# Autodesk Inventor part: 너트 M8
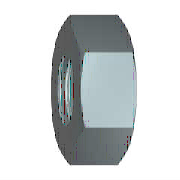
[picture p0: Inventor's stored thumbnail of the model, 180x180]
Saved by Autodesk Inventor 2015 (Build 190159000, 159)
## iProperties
IsCustomPart: 1
Created: 2012-02
Part Number: 너트 M8
Material: 강철, 연강
Description: 6각 너트
Document SubType Name: Modeling
Standard: KS B 1012
Designer: mduedu
Standards Organization: KS
Language: ko-KR
Size Designation: M8
Categories: <MemberInstance><Categories><Category DisplayName="조임쇠" InternalName="e4da775c-781d-43d5-af7c-5136215cf5a6" Mnemonic="FSTN"><Category DisplayName="너트" InternalN
Density: 1 g/cm^3
Appearance: 강철
Author: mduedu
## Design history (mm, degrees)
sketch "스케치1"
  geometry: L1 (-7.506, 0)-(-3.753, 6.5); L2 (-3.753, 6.5)-(3.753, 6.5); L3 (3.753, 6.5)-(7.506, 0); L4 (7.506, 0)-(3.753, -6.5); L5 (3.753, -6.5)-(-3.753, -6.5); L6 (-3.753, -6.5)-(-7.506, 0); 2 further points
  constraints: 12 end point, 1 coincident, 1 horizontal, 11 other
  dimensions: "d0" = 15.01111 distance of L3.end L1.start (= 1.1547 x SW)
extrude "본체" new body sketch "스케치1" distance "d1" = 5 (= KOH); taper "d2" = 0 deg
sketch "스케치2"
  geometry: L1 (0, 3.753)-(0, 7.506) reference; L2 (0, 7.506)-(5, 7.506) reference; L3 (5, 3.753)-(5, 7.506) reference; L4 (-1, 0)-(6, 0) reference; L5 (0.581, 7.506)-(0, 6.5); L6 (4.419, 7.506)-(5, 6.5)
  constraints: 4 end point, 4 point on line
  dimensions: "d3" = 30 deg angle of L1 L5 (= ANG1); "d4" = 30 deg angle of L3 L6 (= ANG2); "d5" = 13 diameter of L5.end L4 (= SW0); "d6" = 13 diameter of L6.end L4 (= SW01)
revolve "모따기1" sketch "스케치2" stored, may be unused: angle "d7" = 90 deg
sketch "스케치3"
  geometry: A1 r 6.5 centre (0, 0) between (-3.25, -5.629) and (3.25, -5.629) reference; 1 further point
  constraints: 1 coincident
hole "스레드" sketch "스케치3" at (0, 0) diameter "d25" = 6.647; stored, may be unused: countersink angle "d29" = 82 deg, drill point angle "d31" = 118 deg; dims "d26" = 6, "d27" = 4, "d28" = 2, "d30" = 8
workaxis "Work Axis1"
workplane "Work Plane1"
body "Solid1"
chamfer "모따기2" distance "d8" = 0.67658 (= -0.5 x GD1 + 0.5 x NND); stored, may be unused: angle "d9" = 30 deg, second distance "d40" = 0.67658 (= -0.5 x GD1 + 0.5 x NND)
chamfer "모따기3" distance "d10" = 0.67658 (= -0.5 x GD1 + 0.5 x NND); stored, may be unused: angle "d11" = 30 deg, second distance "d41" = 0.67658 (= -0.5 x GD1 + 0.5 x NND)
other parameters: "ANG1" = 30 deg [user parameter; used in 1 equation term], "ANG2" = 30 deg [user parameter; used in 1 equation term], "NND" = 8 [user parameter; used in 4 equation terms], "KOH" = 5 [user parameter; used in 1 equation term], "SW" = 13 [user parameter; used in 4 equation terms], "SW0" = 13 (= SW) [user parameter; used in 1 equation term], "SW01" = 13 (= SW) [user parameter; used in 1 equation term], "GD1" = 6.64684 (computed from THREADDIA, PTC, TOA) [user parameter; used in 4 equation terms], "d13" = 0, "d14" = 0, "d39" = 0, "d42" = 0, "GUL" = 0.67658 (= 0.541266 x PTC) [user parameter], "TPU" = 8 (computed from PTC) [user parameter], "THREADDIA" = 8 [user parameter; used in 1 equation term], "TOA" = 30 deg [user parameter; used in 1 equation term], "PTC" = 1.25 [user parameter; used in 4 equation terms], "E0" = 15.015 (= 1.155 x SW) [user parameter], "GAL" = 0.67658 (= 0.541266 x PTC) [user parameter]
